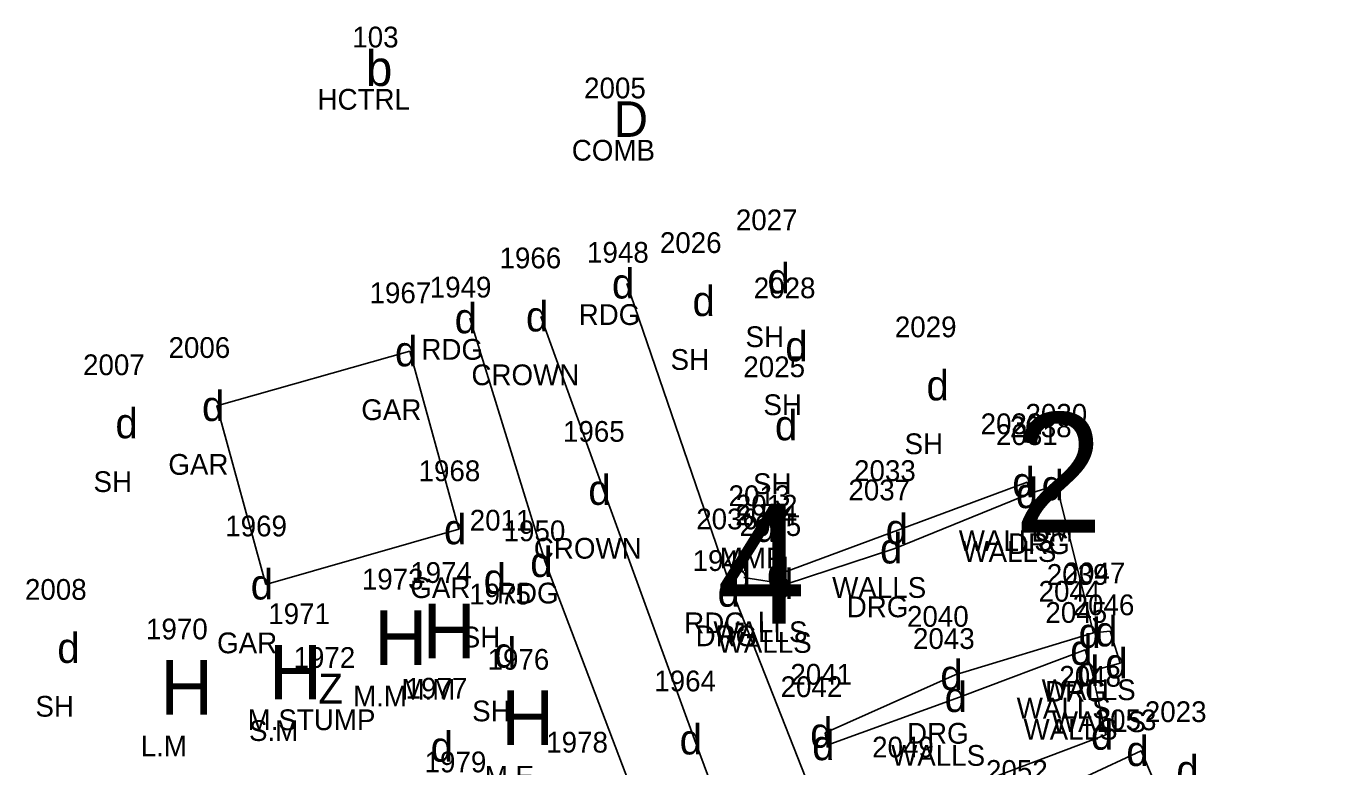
# Model space of a CAD drawing. Extents: x 461160 to 461373, y 202903 to 203086.
# Drawn here: x 461289.17 to 461337.43, y 203059.37 to 203086.48 of the extents above; entities that cross this region are included whole.
import ezdxf

# ---------------------------------------------------------------- set-up
doc = ezdxf.new("R2010")
doc.units = 0
for name, color, linetype in [('Level 1', 7, 'Continuous'), ('Level 11', 7, 'Continuous'), ('Level 12', 7, 'Continuous'), ('Level 13', 7, 'Continuous'), ('Level 14', 7, 'Continuous'), ('Level 15', 7, 'Continuous'), ('Level 46', 7, 'Continuous'), ('Level 47', 7, 'Continuous'), ('Level 48', 7, 'Continuous'), ('Level 49', 7, 'Continuous')]:
    doc.layers.add(name, color=color, linetype=linetype)

msp = doc.modelspace()

# ---------------------------------------------------------------- linework, layer by layer
at = {"layer": 'Level 11'}
for points in [[(461337.431, 203004.112), (461335.803, 203008.917), (461333.619, 203019.078), (461330.951, 203025.095), (461326.97, 203035.309), (461323.195, 203044.309), (461319.052, 203055.572), (461315.04, 203065.78), (461311.172, 203077.068)], [(461305.411, 203075.794), (461308.179, 203066.87), (461311.606, 203057.835), (461315.035, 203048.923), (461318.285, 203040.867), (461321.673, 203032.386), (461324.91, 203024.016), (461327.727, 203015.366), (461329.538, 203007.508), (461329.989, 203003.994)], [(461315.456, 203066.304), (461317.003, 203066.062), (461320.993, 203067.365), (461325.97, 203069.391), (461326.91, 203069.678), (461328.265, 203064.271), (461323.202, 203062.735), (461318.436, 203060.616)], [(461328.21, 203062.88), (461328.721, 203060.543), (461321.865, 203057.949), (461319.365, 203055.979)]]:
    msp.add_lwpolyline(points, dxfattribs=at)
at = {"layer": 'Level 12'}
for points in [[(461325.97, 203069.391), (461325.838, 203069.789), (461321.2, 203068.074), (461316.851, 203066.453), (461317.003, 203066.062)], [(461318.436, 203060.616), (461318.508, 203060.161), (461323.359, 203061.924), (461327.961, 203063.654), (461328.21, 203062.88), (461329.248, 203063.158), (461328.875, 203064.329), (461328.265, 203064.271)], [(461322.062, 203056.369), (461326.035, 203058.094), (461330.017, 203059.947), (461332.352, 203054.423), (461330.058, 203050.812), (461325.12, 203048.8), (461322.062, 203056.369)]]:
    msp.add_lwpolyline(points, dxfattribs=at)
at = {"layer": 'Level 13'}
for points in [[(461303.221, 203074.585), (461296.152, 203072.581), (461297.937, 203066.046)], [(461303.221, 203074.585), (461305.017, 203068.068), (461297.937, 203066.046)]]:
    msp.add_lwpolyline(points, dxfattribs=at)
at = {"layer": 'Level 48'}
msp.add_lwpolyline([(461333.417, 203005.909), (461331.483, 203014.687), (461327.762, 203024.338), (461324.238, 203033.554), (461320.813, 203042.414), (461317.071, 203051.173), (461313.653, 203060.371), (461310.308, 203069.511), (461308.022, 203075.862)], dxfattribs=at)

# ---------------------------------------------------------------- texts
at = {"layer": 'Level 1'}
for s, height, p in [('b', 1.3, (461301.61, 203084.302)), ('2', 4.4, (461325.343, 203067.937))]:
    msp.add_text(s, height=height, dxfattribs=at).set_placement(p)
at = {"layer": 'Level 14'}
for s, height, p in [('H', 2, (461301.922, 203063.1)), ('H', 2, (461303.694, 203063.342)), ('H', 2, (461298.062, 203061.834)), ('H', 2, (461294.077, 203061.274)), ('Z', 1.1, (461299.868, 203061.68)), ('H', 2, (461306.566, 203060.163))]:
    msp.add_text(s, height=height, dxfattribs=at).set_placement(p)
at = {"layer": 'Level 15'}
for s, height, p in [('D', 1.3, (461310.689, 203082.436)), ('4', 4.4, (461314.453, 203064.61))]:
    msp.add_text(s, height=height, dxfattribs=at).set_placement(p)
at = {"layer": 'Level 46'}
for s, p in [(' HCTRL  ', (461299.553, 203083.432)), (' COMB  ', (461308.868, 203081.566)), (' RDG  ', (461309.12, 203075.548)), (' SH  ', (461315.233, 203074.738)), (' RDG  ', (461303.359, 203074.274)), (' SH  ', (461312.488, 203073.904)), (' CROWN  ', (461305.192, 203073.342)), (' GAR  ', (461301.157, 203072.065)), (' SH  ', (461315.889, 203072.247)), (' SH  ', (461321.061, 203070.817)), (' GAR  ', (461294.088, 203070.061)), (' SH  ', (461291.346, 203069.43)), (' SH  ', (461315.508, 203069.356)), (' BM  ', (461325.709, 203067.617)), (' WALLS  ', (461323.047, 203067.269)), (' DRG  ', (461324.858, 203067.158)), (' CROWN  ', (461307.478, 203066.991)), (' MMF  ', (461314.291, 203066.634)), (' WALLS  ', (461323.179, 203066.871)), (' GAR  ', (461302.953, 203065.548)), (' RDG  ', (461306.127, 203065.35)), (' WALLS  ', (461318.409, 203065.554)), (' DRG  ', (461318.941, 203064.845)), (' RDG  ', (461312.988, 203064.26)), (' LI  ', (461315.681, 203064.29)), (' SH  ', (461304.837, 203063.738)), (' DRG  ', (461313.404, 203063.784)), (' WALLS  ', (461314.06, 203063.933)), (' GAR  ', (461295.873, 203063.526)), (' WALLS  ', (461314.212, 203063.542)), (' M.M  ', (461302.627, 203061.822)), (' WALLS  ', (461326.084, 203061.809)), (' M.M  ', (461300.855, 203061.58)), (' DRG  ', (461326.213, 203061.751)), (' SH  ', (461289.217, 203061.203)), (' SH  ', (461305.218, 203061.033)), (' WALLS  ', (461325.17, 203061.134)), (' M.STUMP  ', (461296.99, 203060.71)), (' S.M  ', (461297.043, 203060.314)), (' WALLS  ', (461325.419, 203060.36)), (' WALLS  ', (461326.457, 203060.638)), (' DRG  ', (461321.15, 203060.215)), (' L.M  ', (461293.076, 203059.754)), (' WALLS  ', (461320.568, 203059.404)), (' M.E  ', (461305.678, 203058.643))]:
    msp.add_text(s, height=0.76, dxfattribs=at).set_placement(p)
at = {"layer": 'Level 47'}
for p in [(461310.622, 203076.518), (461316.319, 203076.708), (461313.574, 203075.874), (461304.861, 203075.244), (461307.472, 203075.312), (461302.671, 203074.035), (461316.975, 203074.217), (461322.147, 203072.787), (461295.602, 203072.031), (461292.432, 203071.4), (461316.594, 203071.326), (461325.288, 203069.239), (461326.36, 203069.128), (461309.758, 203068.961), (461325.42, 203068.841), (461304.467, 203067.518), (461315.835, 203067.604), (461320.65, 203067.524), (461320.443, 203066.815), (461307.629, 203066.32), (461314.906, 203065.754), (461316.301, 203065.903), (461297.387, 203065.496), (461305.923, 203065.708), (461314.49, 203065.23), (461316.453, 203065.512), (461327.715, 203063.721), (461328.325, 203063.779), (461290.303, 203063.173), (461306.304, 203063.003), (461327.411, 203063.104), (461328.698, 203062.608), (461322.652, 203062.185), (461327.66, 203062.33), (461322.809, 203061.374), (461317.886, 203060.066), (461328.171, 203059.993), (461303.978, 203059.555), (461313.103, 203059.821), (461317.958, 203059.611), (461329.467, 203059.397), (461331.303, 203058.696)]:
    msp.add_text('d', height=1.1, dxfattribs=at).set_placement(p)
at = {"layer": 'Level 49'}
for s, p in [(' 103 ', (461300.827, 203085.712)), (' 2005 ', (461309.32, 203083.846)), (' 2027 ', (461314.88, 203079.018)), (' 2026 ', (461312.096, 203078.184)), (' 1948 ', (461309.428, 203077.828)), (' 1966 ', (461306.221, 203077.622)), (' 1967 ', (461301.459, 203076.345)), (' 1949 ', (461303.664, 203076.554)), (' 2028 ', (461315.536, 203076.527)), (' 2029 ', (461320.705, 203075.097)), (' 2006 ', (461294.094, 203074.341)), (' 2007 ', (461290.963, 203073.71)), (' 2025 ', (461315.155, 203073.636)), (' 2030 ', (461325.491, 203071.897)), (' 2032 ', (461323.849, 203071.549)), (' 2038 ', (461324.921, 203071.438)), (' 1965 ', (461308.546, 203071.271)), (' 2031 ', (461324.412, 203071.151)), (' 1968 ', (461303.255, 203069.828)), (' 2033 ', (461319.211, 203069.834)), (' 2037 ', (461319.004, 203069.125)), (' 2013 ', (461314.611, 203068.914)), (' 2012 ', (461314.879, 203068.57)), (' 2036 ', (461313.428, 203068.064)), (' 2034 ', (461314.862, 203068.213)), (' 1969 ', (461296.172, 203067.806)), (' 2011 ', (461305.13, 203068.018)), (' 1950 ', (461306.372, 203067.63)), (' 2035 ', (461315.014, 203067.822)), (' 1974 ', (461302.95, 203066.102)), (' 1947 ', (461313.296, 203066.54)), (' 1973 ', (461301.178, 203065.86)), (' 2039 ', (461326.273, 203066.031)), (' 2047 ', (461326.886, 203066.089)), (' 2008 ', (461288.834, 203065.483)), (' 1975 ', (461305.11, 203065.313)), (' 2044 ', (461325.972, 203065.414)), (' 2046 ', (461327.22, 203064.918)), (' 1971 ', (461297.749, 203064.594)), (' 2040 ', (461321.15, 203064.495)), (' 2045 ', (461326.221, 203064.64)), (' 1970 ', (461293.27, 203064.034)), (' 2043 ', (461321.37, 203063.684)), (' 1972 ', (461298.674, 203062.99)), (' 1976 ', (461305.783, 203062.923)), (' 2041 ', (461316.878, 203062.376)), (' 2048 ', (461326.732, 203062.303)), (' 1977 ', (461302.784, 203061.865)), (' 1964 ', (461311.891, 203062.131)), (' 2042 ', (461316.519, 203061.921)), (' 2023 ', (461329.864, 203061.006)), (' 2053 ', (461328.028, 203060.707)), (' 1978 ', (461307.933, 203059.889)), (' 2049 ', (461319.873, 203059.709)), (' 1979 ', (461303.477, 203059.165)), (' 2052 ', (461324.046, 203058.854))]:
    msp.add_text(s, height=0.76, dxfattribs=at).set_placement(p)

doc.saveas('drawing.dxf')
